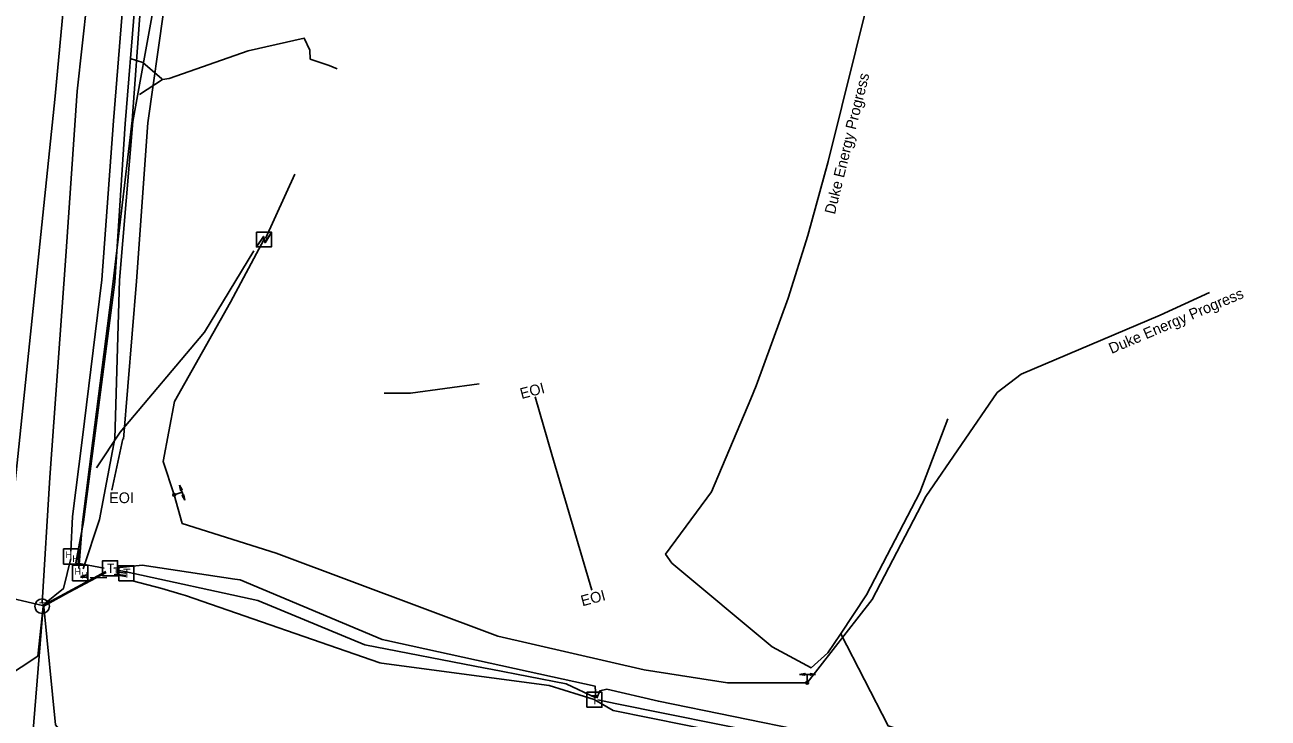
# Model space of a CAD drawing. Extents: x 2070721 to 2083340, y 729290 to 737883.
# Drawn here: x 2082363.4 to 2082825.8, y 736208.1 to 736465.9 of the extents above; entities that cross this region are included whole.
import ezdxf

# ---------------------------------------------------------------- set-up
doc = ezdxf.new("R2010")
doc.units = 0
for name, color, linetype in [('Exist Utilities Other Pole With Base Text', 7, 'Continuous'), ('Exist Utilities Other Unknown UG SUE LOS B', 7, 'Continuous'), ('Exist Utilities Power Change of Service SUE CELL', 7, 'Continuous'), ('Exist Utilities Power Transformer CELL', 7, 'Continuous'), ('Exist Utilities Power UG Cable SUE LOS B', 7, 'Continuous'), ('Exist Utilities Power UG Cable SUE LOS B Text', 7, 'Continuous'), ('Exist Utilities Power UG Cable SUE LOS C', 7, 'Continuous'), ('Exist Utilities Telephone Hand Hole CELL', 7, 'Continuous'), ('Exist Utilities Telephone Manhole CELL', 7, 'Continuous'), ('Exist Utilities Telephone Pedestal CELL', 7, 'Continuous'), ('Exist Utilities Telephone UG Cable SUE LOS C', 7, 'Continuous'), ('Exist Utilities Telephone UG Conduit SUE LOS B', 7, 'Continuous'), ('Exist Utilities Telephone UG FO SUE LOS B', 7, 'Continuous'), ('Exist Utilities Telephone UG FO SUE LOS C', 7, 'Continuous'), ('Exist Utilities TV Hand Hole CELL', 7, 'Continuous'), ('Exist Utilities TV UG FO Cable SUE LOS B', 7, 'Continuous'), ('Exist Utilities Water UG Line SUE LOS B', 7, 'Continuous')]:
    doc.layers.add(name, color=color, linetype=linetype)

msp = doc.modelspace()

# ---------------------------------------------------------------- linework, layer by layer
at = {"layer": 'Exist Utilities Other Unknown UG SUE LOS B'}
for points in [[(2082395.72, 736292.86), (2082399.83, 736311.96), (2082400.03, 736311.89), (2082404.85, 736370.66), (2082409.06, 736429.49), (2082414.93, 736470.65), (2082419.29, 736514.19), (2082420.3, 736517.77)], [(2082574.24, 736255.68), (2082559.38, 736306.12), (2082553.11, 736327.59)], [(2082418.9, 736291.15), (2082421.9, 736280.56), (2082456.86, 736269.48)]]:
    msp.add_lwpolyline(points, dxfattribs=at)
at = {"layer": 'Exist Utilities Power Change of Service SUE CELL'}
for p, q in [((2082418.9, 736291.15), (2082421.83, 736292.12)), ((2082422.82, 736289.15), (2082420.93, 736294.81)), ((2082421.83, 736292.12), (2082422.82, 736289.15)), ((2082418.9, 736291.15), (2082418.9, 736291.15)), ((2082657.47, 736224.38), (2082651.5, 736224.38)), ((2082654.33, 736221.3), (2082654.33, 736224.38)), ((2082654.33, 736224.38), (2082657.47, 736224.38)), ((2082654.33, 736221.3), (2082654.33, 736221.3))]:
    msp.add_line(p, q, dxfattribs=at)
for points in [[(2082420.93, 736294.81), (2082421.88, 736293.05), (2082421.42, 736293.33), (2082421.25, 736292.88)], [(2082422.82, 736289.15), (2082421.87, 736290.91), (2082422.33, 736290.62), (2082422.5, 736291.08)], [(2082651.5, 736224.38), (2082653.47, 736224.73), (2082653.05, 736224.38), (2082653.44, 736224.08)], [(2082657.47, 736224.38), (2082655.49, 736224.04), (2082655.91, 736224.38), (2082655.53, 736224.69)]]:
    msp.add_lwpolyline(points, close=True, dxfattribs=at)
for centre in [(2082418.9, 736291.15), (2082654.33, 736221.3)]:
    msp.add_circle(centre, 0.517, dxfattribs=at)
at = {"layer": 'Exist Utilities Power Transformer CELL'}
msp.add_line((2082452.35, 736386.28), (2082452.35, 736386.28), dxfattribs=at)
msp.add_lwpolyline([(2082449.51, 736388.89), (2082455.06, 736388.89), (2082455.06, 736383.34), (2082449.51, 736383.34)], close=True, dxfattribs=at)
for points in [[(2082449.51, 736383.34), (2082452.15, 736387.28), (2082452.78, 736385.07), (2082455.06, 736388.89)], [(2082449.58, 736383.34), (2082452.15, 736387.07), (2082452.74, 736384.89), (2082455.06, 736388.74)]]:
    msp.add_lwpolyline(points, dxfattribs=at)
at = {"layer": 'Exist Utilities Power UG Cable SUE LOS B'}
for p, q in [((2082463.81, 736410.44), (2082452.84, 736386.5)), ((2082387.6, 736260.34), (2082393.82, 736260.4))]:
    msp.add_line(p, q, dxfattribs=at)
for points in [[(2082633.41, 736326.82), (2082635.39, 736331.76), (2082647.25, 736364.29), (2082654.64, 736387.64), (2082662.17, 736415.15), (2082677.46, 736477.1), (2082686.22, 736495.26), (2082698.83, 736517.21), (2082712.08, 736532.18), (2082721.96, 736540.93)], [(2082414.59, 736445.57), (2082416.98, 736445.94), (2082446.41, 736456.23), (2082467.28, 736460.97), (2082469.35, 736456.58), (2082469.49, 736453.23), (2082476.52, 736450.86), (2082479.53, 736449.61)], [(2082402.51, 736453.49), (2082407.28, 736451.91), (2082414.3, 736445.82), (2082414.59, 736445.57)], [(2082414.59, 736445.57), (2082405.99, 736440.03)], [(2082448.58, 736381.94), (2082430.13, 736351.6), (2082398.76, 736314.47), (2082389.97, 736301.15)], [(2082654.33, 736221.3), (2082678.51, 736252.19), (2082698.5, 736290.59), (2082725, 736329.21), (2082733.89, 736336.05), (2082785.68, 736358.04), (2082804, 736366.39)], [(2082532.37, 736332.5), (2082506.75, 736329), (2082497.01, 736329)], [(2082633.41, 736326.82), (2082618.79, 736292.34), (2082601.67, 736269.13), (2082603.94, 736265.79), (2082641.3, 736234.65), (2082655.87, 736226.86), (2082661.97, 736232.43), (2082666.77, 736239.35), (2082676.44, 736253.93), (2082696.29, 736292.01), (2082706.61, 736319.37)]]:
    msp.add_lwpolyline(points, dxfattribs=at)
at = {"layer": 'Exist Utilities Power UG Cable SUE LOS C'}
for points in [[(2082418.9, 736291.15), (2082414.75, 736303.55), (2082418.98, 736325.85), (2082439.82, 736362.86), (2082452.35, 736386.28)], [(2082456.86, 736269.48), (2082539.23, 736238.57), (2082593.67, 736226.14), (2082624.7, 736221.3), (2082654.33, 736221.3)], [(2082666.83, 736239.42), (2082684.44, 736205.31), (2082720.04, 736193.67), (2082747.93, 736187.86), (2082781.39, 736180)]]:
    msp.add_lwpolyline(points, dxfattribs=at)
at = {"layer": 'Exist Utilities Telephone Hand Hole CELL'}
for p, q in [((2082377.71, 736271.07), (2082377.71, 736265.35)), ((2082383.43, 736271.07), (2082377.71, 736271.07)), ((2082383.43, 736265.35), (2082383.43, 736271.07)), ((2082377.71, 736265.35), (2082383.43, 736265.35)), ((2082380.57, 736268.21), (2082380.57, 736268.21))]:
    msp.add_line(p, q, dxfattribs=at)
at = {"layer": 'Exist Utilities Telephone Manhole CELL'}
msp.add_circle((2082369.79, 736249.74), 2.72, dxfattribs=at)
at = {"layer": 'Exist Utilities Telephone Pedestal CELL'}
for p, q in [((2082395.01, 736263.86), (2082395.01, 736263.86)), ((2082401.04, 736262.02), (2082401.04, 736262.02)), ((2082575.12, 736215.01), (2082575.12, 736215.01))]:
    msp.add_line(p, q, dxfattribs=at)
for points in [[(2082392.29, 736261.03), (2082397.88, 736261.03), (2082397.88, 736266.63), (2082392.29, 736266.63), (2082392.29, 736261.03)], [(2082398.32, 736259.19), (2082403.91, 736259.19), (2082403.91, 736264.79), (2082398.32, 736264.79), (2082398.32, 736259.19)], [(2082572.4, 736212.18), (2082577.99, 736212.18), (2082577.99, 736217.77), (2082572.4, 736217.77), (2082572.4, 736212.18)]]:
    msp.add_lwpolyline(points, dxfattribs=at)
at = {"layer": 'Exist Utilities Telephone UG Cable SUE LOS C'}
for p, q in [((2082393.34, 736262.2), (2082369.98, 736249.96)), ((2082393.52, 736262.7), (2082370.29, 736250.16)), ((2082393.55, 736262.24), (2082370.29, 736249.87)), ((2082400.87, 736260.81), (2082396.53, 736261.53)), ((2082400.91, 736261.12), (2082397.03, 736261.67)), ((2082397.16, 736262.53), (2082400.95, 736262.01)), ((2082401.02, 736262.58), (2082397.18, 736263.21)), ((2082558.33, 736220.24), (2082575.15, 736215.01))]:
    msp.add_line(p, q, dxfattribs=at)
for points in [[(2082392.88, 736263.89), (2082382.27, 736265.88), (2082385.19, 736281.09), (2082389.11, 736311.29), (2082396.78, 736370.29), (2082400.63, 736429.15), (2082404.26, 736473.32), (2082405.87, 736494.42), (2082409.26, 736525.23), (2082412.82, 736576.27), (2082417.8, 736608.3), (2082461.47, 736609.04), (2082528.72, 736605.28), (2082588.4, 736613.3), (2082637.77, 736629.11), (2082670.84, 736641.95), (2082696.51, 736666.16)], [(2082579.78, 736218.88), (2082599.02, 736214.41), (2082710.61, 736191.57), (2082798.37, 736174.45), (2082885.43, 736159.26), (2082946, 736165.14), (2083033.48, 736193.09), (2083077.11, 736211.8), (2083089.57, 736237.13), (2083075.55, 736263.64), (2083044.44, 736310.32), (2083026.72, 736338.29), (2083005.59, 736358.07), (2083003.15, 736369.82)], [(2082396.41, 736263.85), (2082407.06, 736264.95), (2082441.51, 736259.83)], [(2082309.03, 736200.13), (2082349.47, 736218.89), (2082368.17, 736231.22), (2082370.24, 736249.61), (2082392.9, 736262.1)], [(2082401.02, 736262.58), (2082450.02, 736251.87), (2082489.79, 736235.41), (2082534.59, 736226.68), (2082536.66, 736226.37), (2082564.69, 736220.9), (2082575.67, 736215.61)], [(2082441.51, 736259.83), (2082443.48, 736259.57), (2082496.24, 736237.42)], [(2082403.39, 736259.13), (2082414.33, 736256.27), (2082421.34, 736254.2)], [(2082575.12, 736215.01), (2082582.19, 736210.9), (2082636.27, 736200.06), (2082738.67, 736181.25), (2082876.05, 736153.29), (2082889.8, 736152.19), (2082917.84, 736153.8), (2082948.81, 736158.4), (2082968.19, 736165.31), (2083046.85, 736194.42), (2083139.27, 736224.96), (2083160, 736232.47), (2083199.9, 736256.41)], [(2082421.34, 736254.2), (2082423.13, 736253.74), (2082495.39, 736228.71)], [(2082559.58, 736223.51), (2082498, 736237.05), (2082496.24, 736237.42)], [(2082558.33, 736220.24), (2082496.03, 736228.51), (2082495.39, 736228.71)], [(2082559.58, 736223.51), (2082575.46, 736220.04), (2082575.67, 736215.61)], [(2082576.13, 736215.54), (2082577.26, 736218.31), (2082579.78, 736218.88)], [(2082576.46, 736214.97), (2082582.9, 736213.6), (2082698.76, 736190.27)]]:
    msp.add_lwpolyline(points, dxfattribs=at)
at = {"layer": 'Exist Utilities Telephone UG Conduit SUE LOS B'}
for points in [[(2082369.85, 736250.96), (2082372.63, 736297.63), (2082378.59, 736379.94), (2082382.86, 736441.28), (2082390.24, 736508.9), (2082394.52, 736561.91), (2082398.1, 736612.48)], [(2082120.86, 735106.65), (2082121.53, 735109.26), (2082126.82, 735163.37), (2082139.88, 735257.28), (2082147.13, 735321.1), (2082170.45, 735428.84), (2082201.87, 735563.79), (2082232.74, 735685.94), (2082254.12, 735726.65), (2082278.69, 735809.1), (2082319.03, 735920.81), (2082334.41, 735993.71), (2082351.13, 736088.05), (2082365.28, 736188.35), (2082370.12, 736249.49)], [(2082311, 735883.41), (2082314.93, 735894.57), (2082321.33, 735919.82), (2082336.09, 735960.51), (2082359.13, 735988.75), (2082348, 736007.91), (2082360.44, 736082.28), (2082381.79, 736122.83), (2082393.52, 736182.23), (2082374.75, 736205.67), (2082370.42, 736249.5)]]:
    msp.add_lwpolyline(points, dxfattribs=at)
at = {"layer": 'Exist Utilities Telephone UG FO SUE LOS B'}
for points in [[(2082380.42, 736270.25), (2082381.12, 736283.15), (2082384.63, 736311.5), (2082391.98, 736371.16), (2082396.29, 736430.22), (2082399.86, 736473.26), (2082405.23, 736523.1), (2082417.88, 736536.05), (2082427.03, 736545.03), (2082447.47, 736546.52), (2082477.66, 736544.64), (2082535.53, 736545.32), (2082607.76, 736555.33), (2082628.77, 736564.28), (2082669.56, 736584.92)], [(2082370.7, 736250.6), (2082377.71, 736256.3), (2082380.43, 736267.48)], [(2082370.7, 736250.6), (2082377.71, 736256.3), (2082380.43, 736267.48)]]:
    msp.add_lwpolyline(points, dxfattribs=at)
at = {"layer": 'Exist Utilities Telephone UG FO SUE LOS C'}
msp.add_line((2082297.68, 736266.81), (2082369.98, 736249.96), dxfattribs=at)
at = {"layer": 'Exist Utilities TV Hand Hole CELL'}
msp.add_line((2082383.94, 736262.09), (2082383.94, 736262.09), dxfattribs=at)
msp.add_lwpolyline([(2082381.06, 736259.21), (2082386.81, 736259.21), (2082386.81, 736264.96), (2082381.06, 736264.96), (2082381.06, 736259.21)], dxfattribs=at)
at = {"layer": 'Exist Utilities TV UG FO Cable SUE LOS B'}
for p, q in [((2082384.01, 736260.54), (2082386.35, 736260.56)), ((2082384.14, 736260.82), (2082386.4, 736261.38))]:
    msp.add_line(p, q, dxfattribs=at)
for points in [[(2082383.39, 736263.77), (2082384.87, 736281.05), (2082388.71, 736311.38), (2082396.25, 736370.54), (2082403.33, 736430.4), (2082406.33, 736472.77), (2082407.72, 736494.25), (2082413.13, 736522.51), (2082423.07, 736531.36)], [(2082385.03, 736263.7), (2082391.12, 736281.95), (2082396.82, 736312.11), (2082398.55, 736370.94), (2082403.55, 736430), (2082411.08, 736471.72), (2082411.73, 736494.17), (2082412, 736522.79), (2082423.09, 736530.34)]]:
    msp.add_lwpolyline(points, dxfattribs=at)
at = {"layer": 'Exist Utilities Water UG Line SUE LOS B'}
msp.add_lwpolyline([(2082359.3, 736290.13), (2082359.45, 736292.32), (2082374.67, 736439.46), (2082381.09, 736508.57), (2082384.35, 736558.86)], dxfattribs=at)

# ---------------------------------------------------------------- texts
at = {"layer": 'Exist Utilities Other Pole With Base Text'}
for p in [(2082548.13, 736326.77), (2082570.74, 736249.69)]:
    msp.add_text('EOI', height=4, rotation=14.8382, dxfattribs=at).set_placement(p)
at = {"layer": 'Exist Utilities Other Unknown UG SUE LOS B'}
msp.add_text('EOI', height=4, dxfattribs=at).set_placement((2082394.72, 736288.07))
at = {"layer": 'Exist Utilities Power UG Cable SUE LOS B Text'}
for rotation, p in [(76.1342, (2082664.62, 736395.26)), (23.006, (2082767.53, 736343.53))]:
    msp.add_text('Duke Energy Progress', height=4, rotation=rotation, dxfattribs=at).set_placement(p)
at = {"layer": 'Exist Utilities Telephone Hand Hole CELL'}
for p in [(2082378.49, 736267.62), (2082381.06, 736266.15)]:
    msp.add_text('H', height=2.5, dxfattribs=at).set_placement(p)
at = {"layer": 'Exist Utilities Telephone Manhole CELL'}
msp.add_text('T', height=3.5, dxfattribs=at).set_placement((2082368.62, 736247.73))
at = {"layer": 'Exist Utilities Telephone Pedestal CELL'}
for p in [(2082393.88, 736262.15), (2082399.91, 736260.31), (2082573.99, 736213.29)]:
    msp.add_text('T', height=3.42, dxfattribs=at).set_placement(p)
at = {"layer": 'Exist Utilities TV Hand Hole CELL'}
for p in [(2082381.85, 736261.44), (2082384.43, 736259.98)]:
    msp.add_text('H', height=2.5, dxfattribs=at).set_placement(p)

doc.saveas('drawing.dxf')
